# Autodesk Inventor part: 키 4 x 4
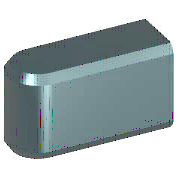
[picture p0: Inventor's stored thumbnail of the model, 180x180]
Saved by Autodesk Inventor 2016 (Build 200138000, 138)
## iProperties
IsCustomPart: 1
Created: 2012-02
Part Number: 키 4 x 4
Material: 강철, 연강
Description: 키 및 해당 키홈
Document SubType Name: Modeling
Standard: KS B 1311
Designer: mduedu
Standards Organization: KS
Language: ko-KR
Size Designation: 4 x 4 x 18
Categories: <MemberInstance><Categories><Category DisplayName="샤프트 부품" InternalName="7f7aeb1f-a693-4053-b835-cee3144e0d98" Mnemonic="SHFT"><Category DisplayName="키" Interna
Density: 1 g/cm^3
Appearance: 주황색
Author: mduedu
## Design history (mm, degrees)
sketch "스케치1"
  geometry: L1 (2, 2)-(18, 2); L2 (18, 2)-(18, -2); L3 (18, -2)-(2, -2); L4 (0, 7)-(0, -7) reference; L5 (-5, 0)-(30, 0) reference; A1 r 2 centre (2, 0) between (2, 2) and (2, -2)
  constraints: 6 end point, 3 tangent, 2 point on circle, 1 centre point, 1 horizontal, 1 parallel, 1 perpendicular, 1 point on line
  dimensions: "d0" = 2 radius of A1 (= 0.5 x PB); "d7" = 18 distance between parallel lines of L2 L4 (= NLG)
workplane "Work Plane1"
workplane "Work Plane2"
extrude "본체1" new body sketch "스케치1" taper "d3" = 0 deg; stored distance "d4" = 10
workaxis "Work Axis1"
workplane "Work Plane4"
body "Solid1"
chamfer "모따기1" distance "d8" = 0.25 (= PHH); stored, may be unused: second distance "d9" = 0.25 (= PHH), angle "d13" = 45 deg
other parameters: "d1" = -2.5 (= -PNT), "d2" = 1.5 (= PH - PNT), "NLG" = 18 [user parameter; used in 2 equation terms], "PB" = 4 [user parameter; used in 1 equation term], "PNT" = 2.5 [user parameter; used in 2 equation terms], "PH" = 4 [user parameter; used in 1 equation term], "PHH" = 0.25 [user parameter; used in 2 equation terms], "d10" = 0, "d16" = 0, "d17" = 0, "d18" = 0, "RR" = 0.08 [user parameter], "WDMAX" = 12 [user parameter], "PLB1" = 18 (= NLG) [user parameter], "PUEB" = 1.8 [user parameter]
